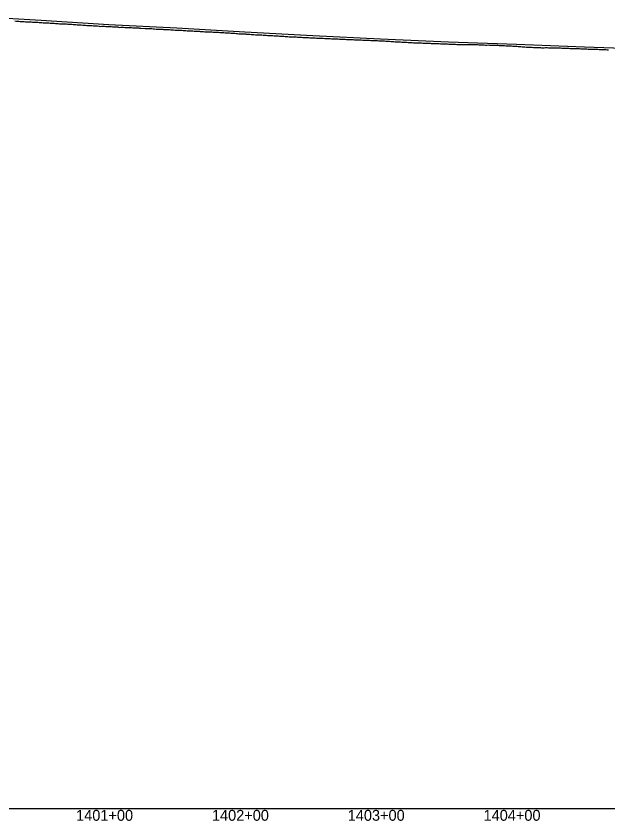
# Model space of a CAD drawing. Extents: x -3793 to 50787, y -1075 to 6138.
# Drawn here: x 27358 to 27793, y 2991 to 3584 of the extents above; entities that cross this region are included whole.
import ezdxf

# ---------------------------------------------------------------- set-up
doc = ezdxf.new("R2010")
doc.units = 0
for name, color, linetype in [('RD_DDB_Profile_EX', 7, 'Continuous'), ('RD_DDB_Profile_PR', 7, 'Continuous'), ('RD_DDB_StaTX', 7, 'Continuous'), ('RD_GPK_Profile_Cell', 7, 'Continuous')]:
    doc.layers.add(name, color=color, linetype=linetype)

msp = doc.modelspace()

# ---------------------------------------------------------------- linework, layer by layer
at = {"layer": 'RD_DDB_Profile_EX'}
for points in [[(27356.532731, 3579.992865), (27357.692262, 3579.928915), (27358.528102, 3579.88718), (27359.530871, 3579.83707), (27360.533343, 3579.73716), (27361.526167, 3579.68664), (27362.526254, 3579.63833), (27363.529024, 3579.54376), (27364.530423, 3579.49377), (27365.524251, 3579.39308)], [(27365.524251, 3579.39308), (27366.526659, 3579.38742), (27367.528003, 3579.337215), (27368.530708, 3579.29239), (27369.524529, 3579.23621), (27370.525879, 3579.141495), (27371.528269, 3579.085805), (27372.53091, 3579.079775), (27373.523608, 3579.02884), (27374.525955, 3578.983925), (27375.528301, 3578.939), (27376.529602, 3578.88314), (27377.53195, 3578.738195), (27378.000647, 3578.7386), (27378.523271, 3578.738795), (27379.525266, 3578.68298), (27380.527261, 3578.58259), (27381.526865, 3578.52837), (27382.526468, 3578.468625), (27383.526071, 3578.386235), (27384.770109, 3578.324035), (27385.52762, 3578.281385), (27386.527163, 3578.232355), (27387.526706, 3578.183325), (27388.528637, 3578.04381), (27389.528179, 3577.994825), (27390.527721, 3577.95143), (27391.539571, 3577.840745), (27392.530513, 3577.801455), (27393.530001, 3577.796655), (27394.529489, 3577.791815), (27395.531356, 3577.69098), (27396.530843, 3577.647375), (27397.53033, 3577.59252), (27398.529805, 3577.581925), (27399.531615, 3577.480915), (27400.531045, 3577.392725), (27401.530475, 3577.29327), (27402.529905, 3577.238145), (27403.531716, 3577.142755), (27404.531145, 3577.126325), (27405.078494, 3577.09922), (27405.53055, 3577.08241), (27406.529925, 3576.994065), (27407.531985, 3576.942575), (27408.53136, 3576.842895), (27409.530735, 3576.793215), (27410.53011, 3576.743535), (27411.531868, 3576.69225), (27411.847956, 3576.676535), (27412.531206, 3576.63678), (27413.521971, 3576.58636), (27414.52238, 3576.536515), (27415.524075, 3576.52944), (27416.523397, 3576.42953), (27417.52272, 3576.335225), (27418.617418, 3576.26136), (27419.523693, 3576.055885), (27420.522962, 3576.09463), (27421.522232, 3576.08894), (27422.524177, 3576.08148), (27423.523447, 3575.98135), (27424.522716, 3575.93673), (27425.521979, 3575.88657), (27426.523581, 3575.87914), (27427.522799, 3575.82879), (27428.522018, 3575.728445), (27429.521237, 3575.722665), (27430.522845, 3575.67616), (27431.522064, 3575.63119), (27432.521265, 3575.575385), (27433.520434, 3575.30158), (27434.522, 3575.33856), (27435.52117, 3575.456225), (27436.521358, 3575.366305), (27437.520806, 3575.320825), (27438.517584, 3575.271845), (27438.925803, 3575.27257), (27439.522955, 3575.267935), (27440.519685, 3575.22405), (27441.525027, 3575.16999), (27442.521757, 3575.120765), (27443.418833, 3575.07754), (27445.695265, 3574.96494), (27446.113569, 3574.944155), (27446.486965, 3574.907125), (27446.858792, 3574.90732), (27447.233269, 3574.889185), (27447.601409, 3574.85256), (27447.971061, 3574.83473), (27448.335573, 3574.816745), (27448.692586, 3574.7998), (27449.053737, 3574.800515), (27449.411504, 3574.74663), (27452.521038, 3574.54714), (27453.526244, 3574.49238), (27454.522895, 3574.48709), (27455.519546, 3574.443085), (27456.525535, 3574.34989), (27457.521884, 3574.34476), (27458.527566, 3574.24609)], [(27458.527566, 3574.24609), (27459.523902, 3574.19658), (27460.529846, 3574.01475), (27461.526151, 3574.00934), (27462.519771, 3573.961565), (27463.525715, 3573.956675), (27464.52202, 3573.907015), (27465.527964, 3573.857935), (27466.00365, 3573.834225), (27466.524248, 3573.80816), (27467.521328, 3573.758555), (27468.526097, 3573.66507), (27469.523496, 3573.609365), (27470.528262, 3573.60999), (27471.525347, 3573.55447), (27472.773112, 3573.48109), (27473.523972, 3573.412575), (27474.521345, 3573.324465), (27475.526056, 3573.31293), (27476.523111, 3573.263105), (27477.527819, 3573.25751), (27478.525196, 3573.20148), (27479.542574, 3573.14928), (27480.526921, 3573.063805), (27481.523105, 3573.00748), (27482.528928, 3572.90771), (27483.525112, 3572.857375), (27484.521296, 3572.807045), (27485.524434, 3572.80305), (27486.520611, 3572.746665), (27487.526395, 3572.658705), (27488.522542, 3572.55815), (27489.528004, 3572.558375), (27490.524151, 3572.46981), (27491.521451, 3572.463315), (27492.526082, 3572.413255), (27493.081497, 3572.3293), (27493.523364, 3572.27459), (27494.527641, 3572.22452), (27495.523753, 3572.255835), (27496.521009, 3572.02886), (27497.523246, 3572.02432), (27498.520185, 3572.105935), (27499.52242, 3572.051255), (27499.850959, 3572.035385), (27500.525782, 3571.996435), (27501.519497, 3571.946995), (27502.525209, 3571.85259), (27503.527075, 3571.71594), (27504.521958, 3571.754485), (27505.524144, 3571.755535), (27506.620421, 3571.73621), (27507.523218, 3571.61178), (27508.525364, 3571.47484), (27509.520228, 3571.41917), (27510.522372, 3571.413895), (27511.525697, 3571.370965), (27512.519055, 3571.2839), (27513.52473, 3571.264695), (27514.526835, 3571.171485), (27515.520493, 3571.027795), (27516.523787, 3570.94089), (27517.525553, 3570.92939), (27518.52276, 3570.91561), (27519.524862, 3570.866225), (27520.519703, 3570.77874), (27521.52144, 3570.63559), (27522.524705, 3570.623645), (27523.520687, 3570.61578), (27524.523951, 3570.522435), (27525.526021, 3570.47904), (27526.519317, 3570.42918), (27526.928806, 3570.40906), (27527.522564, 3570.373315), (27528.527488, 3570.27861), (27529.521948, 3570.190975), (27530.524518, 3570.04793), (27531.527086, 3570.1238), (27532.520352, 3570.023715), (27533.698268, 3569.911585), (27534.519382, 3569.841445), (27535.522256, 3569.785505), (27536.524797, 3569.77978), (27537.5189, 3569.72977), (27538.521775, 3569.680025), (27539.526668, 3569.578865), (27540.520768, 3569.485035), (27541.523616, 3569.522665), (27542.524937, 3569.391445), (27543.519012, 3569.3788), (27544.524216, 3569.32717), (27545.518285, 3569.18923), (27546.520803, 3569.221015), (27547.523644, 3569.164815), (27548.517687, 3569.12665), (27549.522534, 3569.0189), (27550.525357, 3569.01869), (27551.518218, 3568.924245), (27552.520714, 3568.868165), (27553.523537, 3568.780135), (27554.006653, 3568.75455)], [(27554.006653, 3568.75455), (27554.519918, 3568.72177), (27555.522393, 3568.67155), (27556.516718, 3568.614585), (27557.519194, 3568.56437), (27558.521671, 3568.42616), (27559.518345, 3568.41752), (27560.776115, 3568.385605), (27561.642021, 3568.31662), (27562.644842, 3568.26593), (27563.714925, 3568.209185), (27564.717282, 3568.20285), (27565.72163, 3568.10662), (27566.715363, 3568.011475), (27567.71771, 3568.010965), (27568.720257, 3567.960035), (27569.712782, 3567.908755), (27570.715071, 3567.858045), (27571.710709, 3567.80511), (27572.713001, 3567.74874), (27573.715295, 3567.69804), (27574.708895, 3567.696745), (27575.711367, 3567.63443), (27576.71559, 3567.587445), (27577.709126, 3567.580545), (27578.711351, 3567.440575), (27579.713578, 3567.395075), (27580.707102, 3567.382765), (27581.0845, 3567.363515), (27581.709284, 3567.33169), (27582.713448, 3567.27886), (27583.707116, 3567.227), (27584.709275, 3567.22058), (27585.702691, 3567.168955), (27586.703838, 3567.07294), (27587.853962, 3567.05862), (27588.701364, 3567.008055), (27589.703464, 3566.96175), (27590.705791, 3566.7852), (27591.699101, 3566.90831), (27592.699184, 3566.85858), (27593.701285, 3566.762125), (27594.701363, 3566.757445), (27595.701376, 3566.707485), (27596.70139, 3566.61247), (27597.703423, 3566.60591), (27598.703656, 3566.595975), (27599.70367, 3566.50582), (27600.703683, 3566.45586), (27601.703675, 3566.450935), (27602.696826, 3566.393815), (27603.69677, 3566.39364), (27604.695986, 3566.302905), (27605.696147, 3566.252545), (27606.696307, 3566.19737), (27607.697557, 3566.15011), (27608.162347, 3566.150025), (27608.69768, 3566.14488), (27609.697771, 3566.09905), (27610.697861, 3566.04847), (27611.699064, 3566.041505), (27612.699153, 3565.986285), (27613.699032, 3565.935895), (27614.931809, 3565.923525), (27615.698253, 3565.884585), (27616.691446, 3565.831785), (27617.691462, 3565.781025), (27618.690596, 3565.734725), (27619.690611, 3565.68395), (27620.690625, 3565.587645), (27621.70127, 3565.539545), (27622.691769, 3565.52975), (27623.691717, 3565.5244), (27624.691663, 3565.427775), (27625.692823, 3565.370855), (27626.692768, 3565.36565), (27627.692711, 3565.323165), (27628.691819, 3565.272095), (27629.691701, 3565.2209), (27630.684688, 3565.167625), (27631.557651, 3565.072785), (27632.556643, 3565.021525), (27633.556437, 3564.97031), (27634.556229, 3564.919095), (27635.55325, 3564.82347), (27636.525952, 3564.768585), (27637.525779, 3564.7673), (27638.523284, 3564.75969), (27639.523109, 3564.574315), (27640.523133, 3564.56889), (27641.520635, 3564.51534), (27642.009656, 3564.51471), (27642.520444, 3564.506135), (27643.106286, 3564.45602), (27644.103794, 3564.41007), (27645.101469, 3564.360085), (27646.108002, 3564.26461), (27647.105511, 3564.26084), (27648.10302, 3564.207065), (27649.109524, 3564.061525), (27650.106963, 3564.01146)], [(27650.106963, 3564.01146), (27651.103799, 3563.95729), (27652.101238, 3563.865085), (27653.107692, 3563.90366), (27654.095793, 3563.899905), (27655.093829, 3563.94606), (27655.548579, 3563.92371), (27656.10005, 3563.892465), (27657.097081, 3563.75038), (27658.095062, 3563.70424), (27659.092094, 3563.65819), (27660.099061, 3563.60457), (27661.096092, 3563.6006), (27662.318041, 3563.54342), (27663.100046, 3563.50077), (27664.0972, 3563.49648), (27665.094948, 3563.442365), (27666.0921, 3563.48811), (27667.098834, 3563.396245), (27668.095987, 3563.29987), (27669.09314, 3563.29954), (27670.099819, 3563.24959), (27671.094856, 3563.15452), (27672.092549, 3563.154145), (27673.089645, 3563.153605), (27674.095556, 3563.05756), (27675.093422, 3563.05704), (27676.090331, 3563.00657), (27677.097133, 3562.95628), (27678.094003, 3562.905645), (27679.091804, 3562.90492), (27680.088846, 3562.858005), (27681.094723, 3562.807805), (27682.092517, 3562.757055), (27682.626426, 3562.756635), (27683.089365, 3562.75249), (27684.161235, 3562.79962), (27685.167081, 3562.79157), (27686.161986, 3562.78829), (27687.166453, 3562.74712), (27688.17034, 3562.748105), (27689.395888, 3562.6955), (27690.169679, 3562.66149), (27691.164364, 3562.66203), (27692.190372, 3562.71293), (27693.185911, 3562.70952), (27694.191595, 3562.69699), (27695.187132, 3562.605485), (27696.190905, 3562.652405), (27697.186381, 3562.606765), (27698.19008, 3562.557495), (27699.185728, 3562.55366), (27700.19022, 3562.50847), (27701.184909, 3562.408785), (27702.189401, 3562.40546), (27703.184073, 3562.30981), (27704.190393, 3562.304765), (27705.194014, 3562.355275), (27706.189436, 3562.30542), (27707.193224, 3562.301695), (27708.188649, 3562.251835), (27709.192264, 3562.25645), (27709.704273, 3562.230765), (27710.18766, 3562.21061), (27711.191206, 3562.156805), (27712.186569, 3562.102625), (27713.190114, 3562.06119), (27714.187374, 3562.009605), (27715.191095, 3561.95569), (27716.473735, 3561.88733), (27717.189957, 3561.8558), (27718.185249, 3561.805545), (27719.188735, 3561.75156), (27720.184027, 3561.701315), (27721.187514, 3561.655515), (27722.191802, 3561.64747), (27723.243197, 3561.540315), (27724.192593, 3561.44966), (27725.18781, 3561.361315), (27726.191245, 3561.361225), (27727.186459, 3561.294675), (27728.189896, 3561.25262), (27729.185108, 3561.206175), (27730.188537, 3561.06405), (27731.214213, 3560.96333), (27732.138446, 3560.871035), (27733.213874, 3560.768825), (27734.139261, 3560.768565), (27735.212846, 3560.760135), (27736.41551, 3560.71079), (27736.78212, 3560.692435), (27737.419448, 3560.660515), (27738.41252, 3560.565295), (27739.414031, 3560.566415), (27740.417939, 3560.55815), (27741.420225, 3560.509255), (27742.413311, 3560.41808), (27743.551582, 3560.40564), (27744.418651, 3560.326685), (27745.420707, 3560.319735), (27746.413086, 3560.324245)], [(27746.413086, 3560.324245), (27747.416913, 3560.369615), (27748.418969, 3560.358505), (27749.421183, 3560.31346), (27750.413398, 3560.309915), (27751.417305, 3560.30904), (27752.419286, 3560.263935), (27753.420458, 3560.26472), (27754.415341, 3560.305235), (27755.417322, 3560.2978), (27756.419462, 3560.202535), (27757.422379, 3560.147635), (27758.415259, 3560.14781), (27759.417324, 3560.10235), (27760.418419, 3560.10288), (27761.422256, 3560.00596), (27762.415137, 3560.002035), (27763.417044, 3559.910845), (27763.859967, 3559.91037), (27764.420029, 3559.905525), (27765.421861, 3559.81411), (27766.414827, 3559.677065), (27767.415854, 3559.73556), (27768.419459, 3559.754985), (27769.421449, 3559.70523), (27770.629429, 3559.689875), (27771.411909, 3559.65802), (27772.413503, 3559.61646), (27773.415258, 3559.562585), (27774.407994, 3559.512365), (27775.41157, 3559.460975), (27776.413166, 3559.45727), (27777.414128, 3559.40338), (27777.795344, 3559.402335), (27778.794883, 3559.307865), (27779.79658, 3559.31189), (27780.796122, 3559.359365), (27781.797627, 3559.30539), (27782.797172, 3559.161), (27783.79672, 3559.158345), (27784.168352, 3559.15834), (27784.798405, 3559.166525), (27785.796925, 3559.167975), (27786.798605, 3559.117745), (27787.798133, 3559.06486), (27788.799813, 3559.060415), (27789.799144, 3559.011825), (27790.937814, 3558.950685), (27791.800343, 3558.912705), (27792.802006, 3558.86656), (27793.801525, 3558.821955)]]:
    msp.add_lwpolyline(points, dxfattribs=at)
at = {"layer": 'RD_DDB_Profile_PR'}
msp.add_lwpolyline([(27325.9, 3583.6015), (27375.9, 3580.5185), (27425.9, 3577.484), (27475.9, 3574.8945), (27525.9, 3572.0605), (27575.9, 3569.226), (27625.9, 3566.97), (27675.9, 3564.6165), (27725.9, 3562.9615), (27775.9, 3561.059), (27825.9, 3559.3045), (27875.9, 3557.8315), (27925.9, 3556.4725), (27975.9, 3555.061), (28025.9, 3553.7145)], dxfattribs=at)
at = {"layer": 'RD_GPK_Profile_Cell'}
msp.add_line((1000, 3000), (46549.603806, 3000), dxfattribs=at)

# ---------------------------------------------------------------- texts
at = {"layer": 'RD_DDB_StaTX'}
for s, p in [('1401+00', (27401.687695, 2991)), ('1401+00', (27401.695471, 2991)), ('1402+00', (27501.687695, 2991)), ('1402+00', (27501.695471, 2991)), ('1403+00', (27601.687695, 2991)), ('1403+00', (27601.695471, 2991)), ('1404+00', (27701.687695, 2991)), ('1404+00', (27701.695471, 2991))]:
    msp.add_text(s, height=8, dxfattribs=at).set_placement(p)

doc.saveas('drawing.dxf')
